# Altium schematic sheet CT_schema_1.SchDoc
size 540 x 499 mm
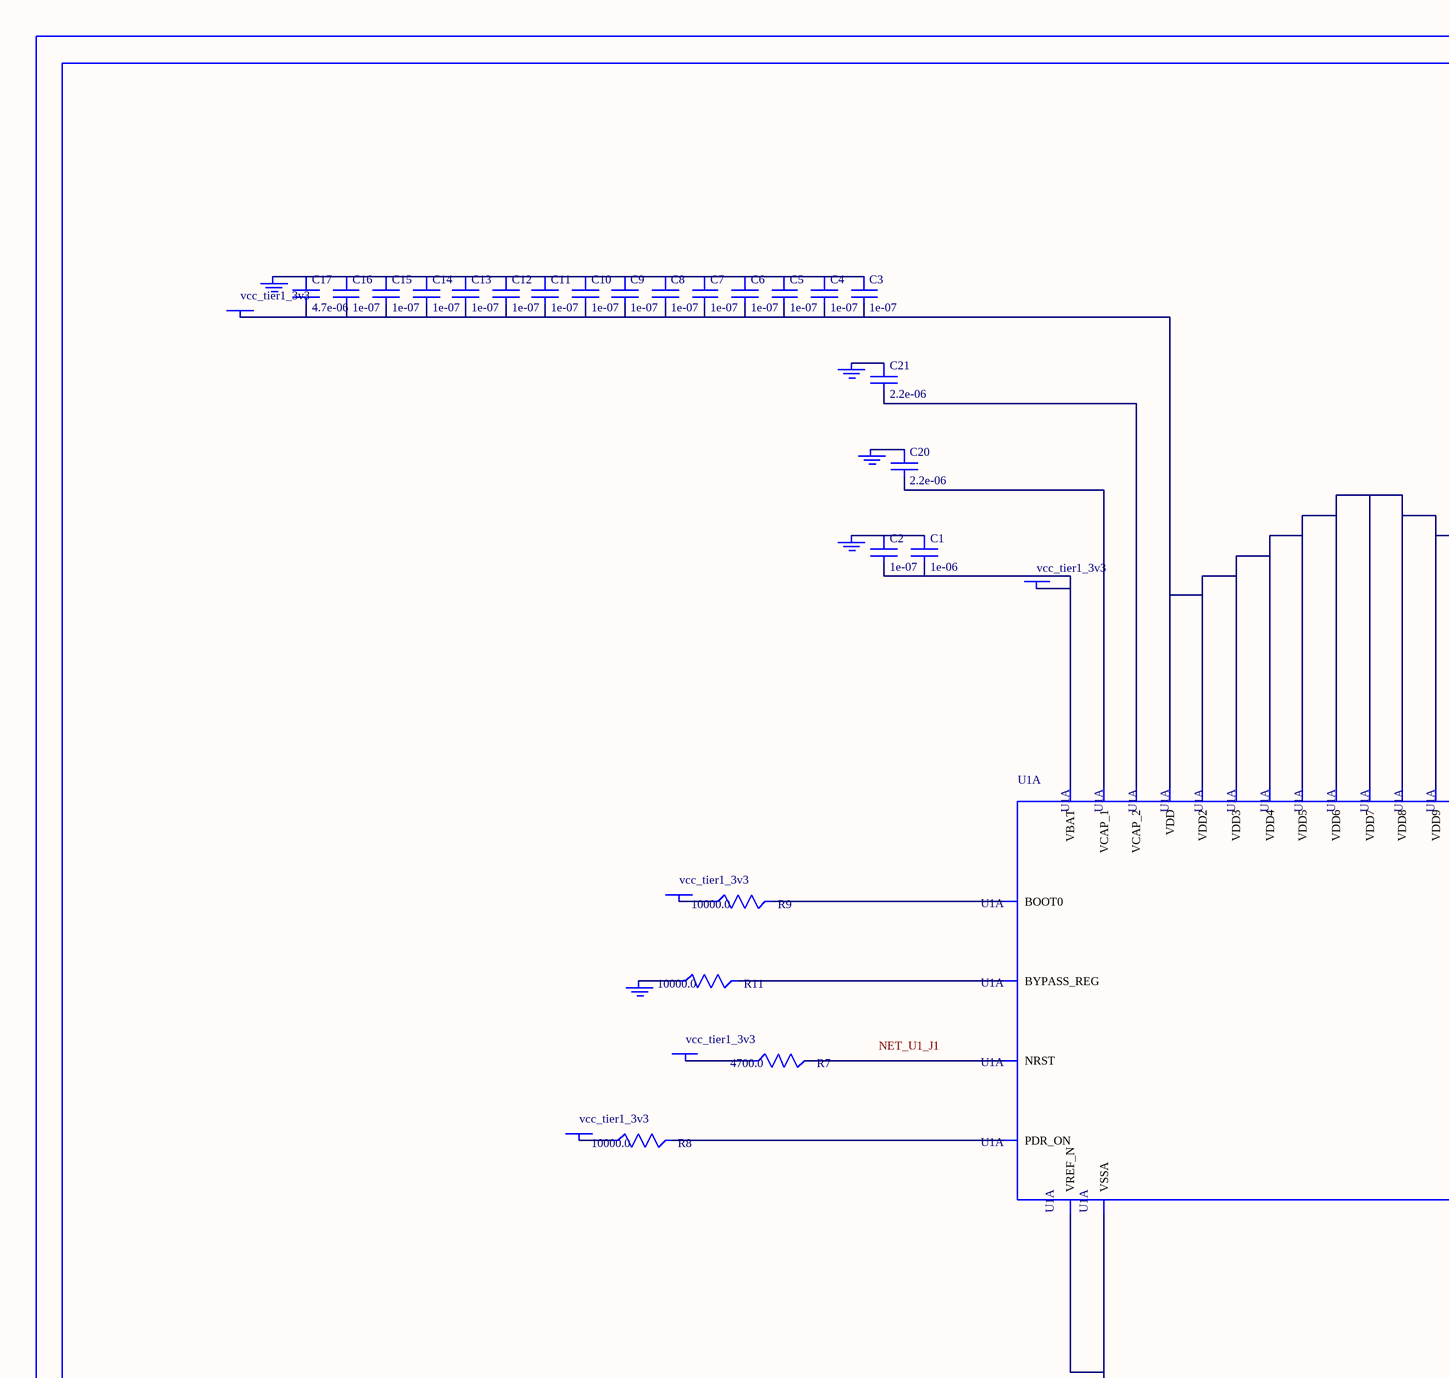
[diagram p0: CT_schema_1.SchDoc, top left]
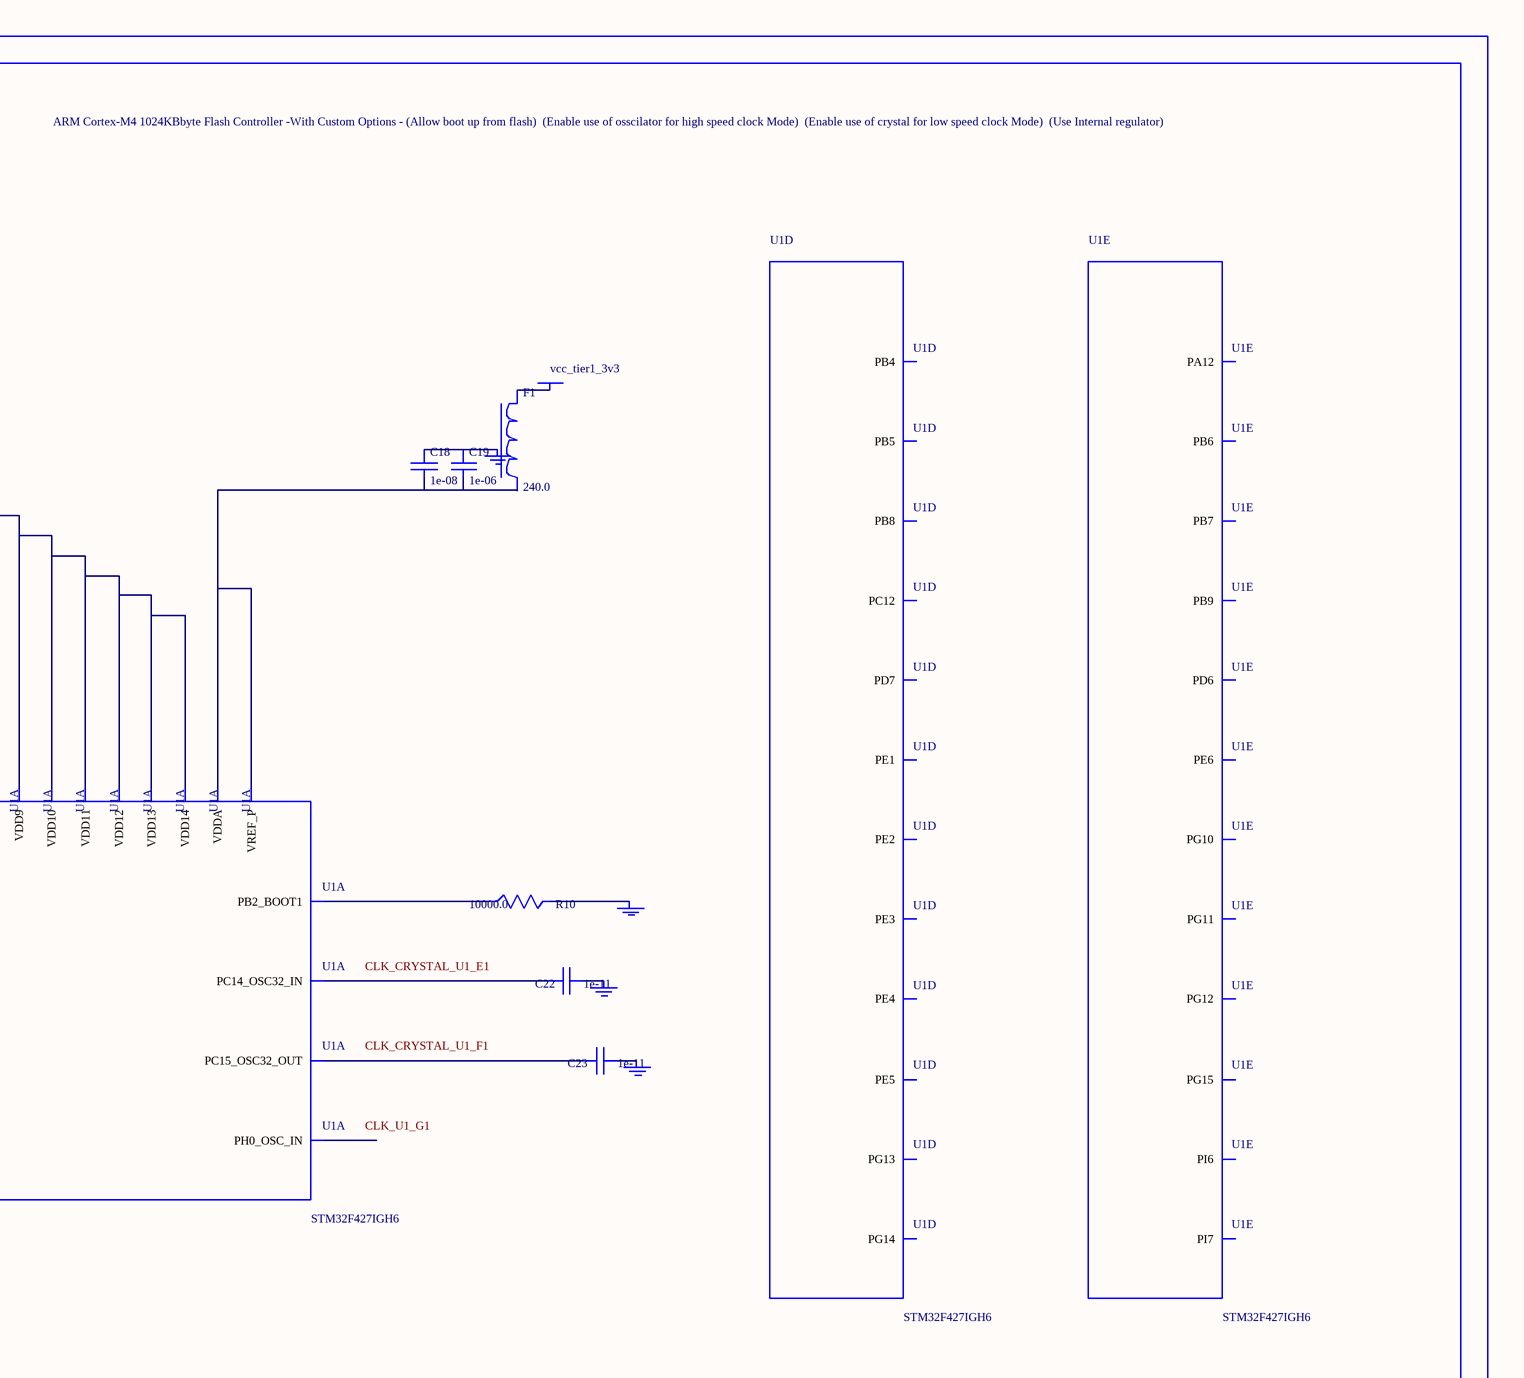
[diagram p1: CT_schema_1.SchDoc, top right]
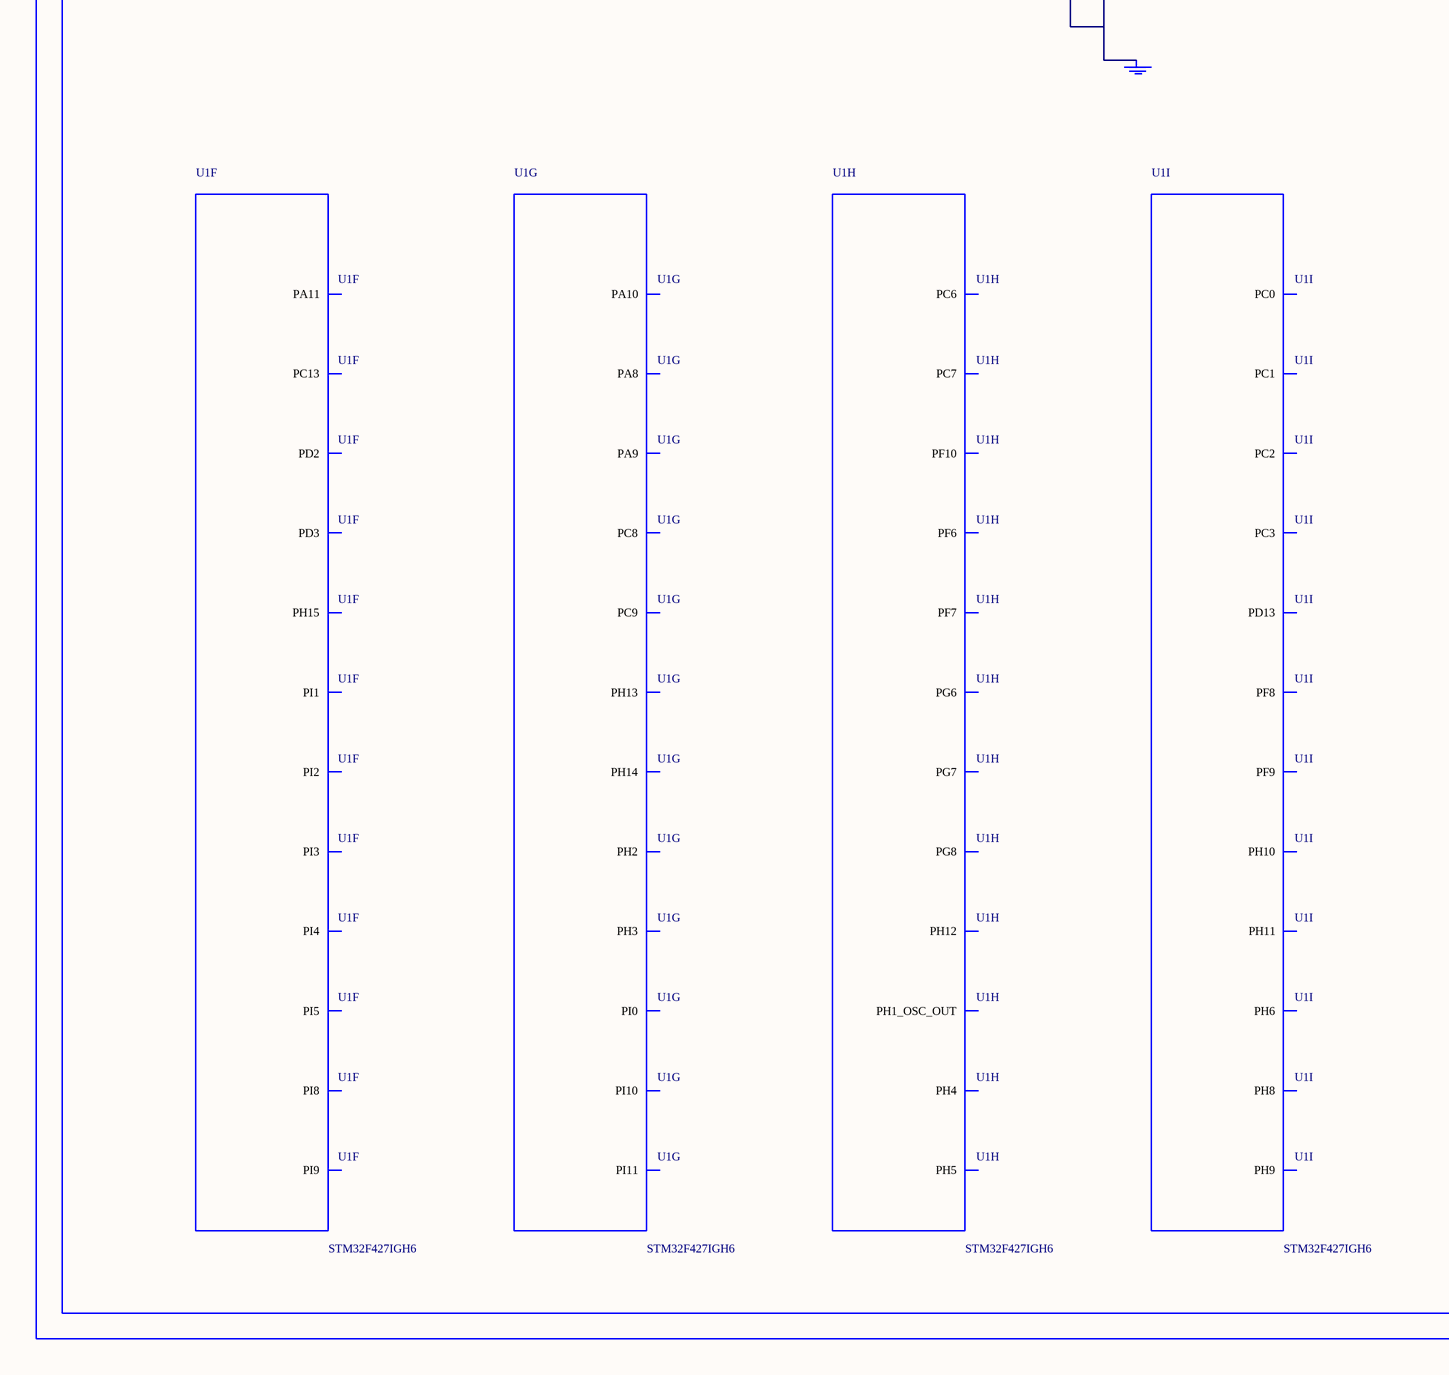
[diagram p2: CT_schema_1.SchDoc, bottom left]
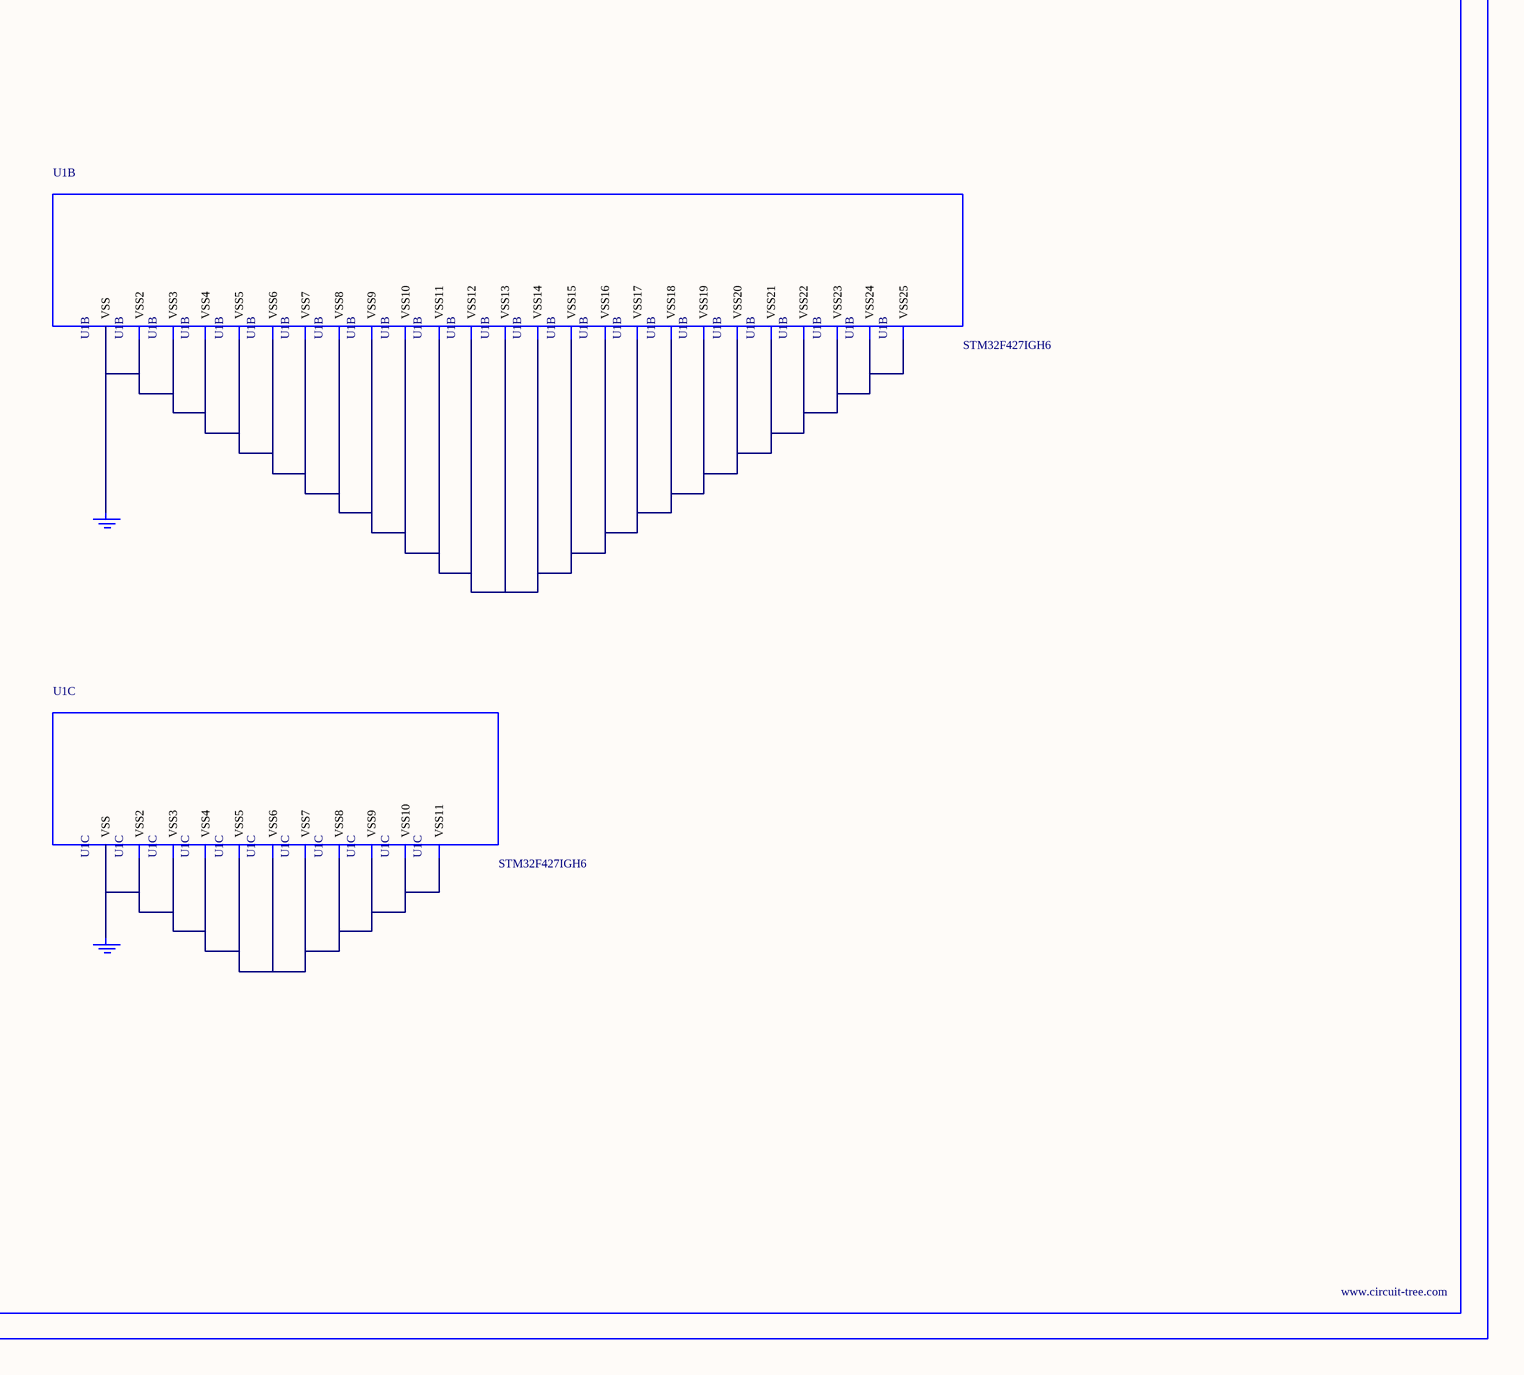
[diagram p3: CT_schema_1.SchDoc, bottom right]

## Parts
BORDER0  (no value)
C1  1e-06  [C0603]
C2  1e-07  [C0603]
C3  1e-07  [C0603]
C4  1e-07  [C0603]
C5  1e-07  [C0603]
C6  1e-07  [C0603]
C7  1e-07  [C0603]
C8  1e-07  [C0603]
C9  1e-07  [C0603]
C10  1e-07  [C0603]
C11  1e-07  [C0603]
C12  1e-07  [C0603]
C13  1e-07  [C0603]
C14  1e-07  [C0603]
C15  1e-07  [C0603]
C16  1e-07  [C0603]
C17  4.7e-06  [C0603]
C18  1e-08  [C0603]
C19  1e-06  [C0603]
C20  2.2e-06  [C0603]
C21  2.2e-06  [C0603]
C22  1e-11  [C0402]
C23  1e-11  [C0402]
F1  240.0  [L0603]
GND_INSTANCE_0_0  (no value)
GND_INSTANCE_0_1  (no value)
GND_INSTANCE_0_2  (no value)
GND_INSTANCE_0_3  (no value)
GND_INSTANCE_0_4  (no value)
GND_INSTANCE_0_5  (no value)
GND_INSTANCE_0_6  (no value)
GND_INSTANCE_0_7  (no value)
GND_INSTANCE_0_8  (no value)
GND_INSTANCE_0_9  (no value)
GND_INSTANCE_0_10  (no value)
GND_INSTANCE_0_11  (no value)
POWER_INSTANCE_0_0  vcc_tier1_3v3
POWER_INSTANCE_0_1  vcc_tier1_3v3
POWER_INSTANCE_0_2  vcc_tier1_3v3
POWER_INSTANCE_0_3  vcc_tier1_3v3
POWER_INSTANCE_0_4  vcc_tier1_3v3
POWER_INSTANCE_0_5  vcc_tier1_3v3
R7  4700.0  [R0603]
R8  10000.0  [R0603]
R9  10000.0  [R0603]
R10  10000.0  [R0603]
R11  10000.0  [R0603]
U1  STM32F427IGH6  [UFBGA176_25]  (parts A,B,C,D,E,F,G,H,I of 16)

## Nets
NetC1_1: C1.1 C2.1 GND_INSTANCE_0_0.0(GND)
NetC1_2: C1.2 C2.2 POWER_INSTANCE_0_0.0(PWR) U1.C1(VBAT)
NetC3_1: C3.1 C4.1 C5.1 C6.1 C7.1 C8.1 C9.1 C10.1 C11.1 C12.1 C13.1 C14.1 C15.1 C16.1 C17.1 GND_INSTANCE_0_2.0(GND)
NetC3_2: C3.2 C4.2 C5.2 C6.2 C7.2 C8.2 C9.2 C10.2 C11.2 C12.2 C13.2 C14.2 C15.2 C16.2 C17.2 POWER_INSTANCE_0_2.0(PWR) U1.C5(VDD) U1.C7(VDD2) U1.C8(VDD3) U1.C9(VDD4) U1.F3(VDD5) U1.G3(VDD7) U1.G13(VDD6) U1.H13(VDD8) U1.J12(VDD9) U1.J13(VDD10) U1.K4(VDD11) U1.N8(VDD13) U1.N9(VDD14) U1.N10(VDD12)
NetC18_1: C18.1 C19.1 GND_INSTANCE_0_1.0(GND)
NetC18_2: C18.2 C19.2 U1.P1(VREF_P) U1.R1(VDDA)
NetC20_1: C20.1 GND_INSTANCE_0_5.0(GND)
NetC20_2: C20.2 U1.M10(VCAP_1)
NetC21_1: C21.1 GND_INSTANCE_0_6.0(GND)
NetC21_2: C21.2 U1.F13(VCAP_2)
NetC22_1: C22.1 GND_INSTANCE_0_7.0(GND)
NetC22_2: C22.2 U1.E1(PC14_OSC32_IN)
NetC23_1: C23.1 GND_INSTANCE_0_8.0(GND)
NetC23_2: C23.2 U1.F1(PC15_OSC32_OUT)
NetF1_1: F1.1 POWER_INSTANCE_0_1.0(PWR)
NetGND_INSTANCE_0_3_0: GND_INSTANCE_0_3.0(GND) R10.2
NetGND_INSTANCE_0_4_0: GND_INSTANCE_0_4.0(GND) R11.1
NetGND_INSTANCE_0_9_0: GND_INSTANCE_0_9.0(GND) U1.M1(VSSA) U1.N1(VREF_N)
NetGND_INSTANCE_0_10_0: GND_INSTANCE_0_10.0(GND) U1.D5(VSS) U1.D7(VSS2) U1.D8(VSS3) U1.D9(VSS4) U1.F2(VSS7) U1.F6(VSS8) U1.F7(VSS9) U1.F8(VSS10) U1.F9(VSS11) U1.F10(VSS5) U1.F12(VSS6) U1.G2(VSS14) U1.G6(VSS15) U1.G7(VSS16) U1.G8(VSS17) U1.G9(VSS18) U1.G10(VSS12) U1.G12(VSS13) U1.H6(VSS21) U1.H7(VSS22) U1.H8(VSS23) U1.H9(VSS24) U1.H10(VSS19) U1.H12(VSS20) U1.J10(VSS25)
NetGND_INSTANCE_0_11_0: GND_INSTANCE_0_11.0(GND) U1.J6(VSS) U1.J7(VSS2) U1.J8(VSS3) U1.J9(VSS4) U1.K6(VSS6) U1.K7(VSS7) U1.K8(VSS8) U1.K9(VSS9) U1.K10(VSS5) U1.M8(VSS10) U1.M9(VSS11)
NetPOWER_INSTANCE_0_3_0: POWER_INSTANCE_0_3.0(PWR) R8.1
NetPOWER_INSTANCE_0_4_0: POWER_INSTANCE_0_4.0(PWR) R9.1
NetPOWER_INSTANCE_0_5_0: POWER_INSTANCE_0_5.0(PWR) R7.1
NetR7_2: R7.2 U1.J1(NRST)
NetR8_2: R8.2 U1.C6(PDR_ON)
NetR9_2: R9.2 U1.D6(BOOT0)
NetR10_1: R10.1 U1.M6(PB2_BOOT1)
NetR11_2: R11.2 U1.L4(BYPASS_REG)

Not connected (* = marked no-connect by the designer): F1 2; U1 A1(PE3) A2(PE2) A3(PE1) A5(PB8) A6(PB5) A7(PG14) A8(PG13) A9(PB4) A11(PD7) A12(PC12) B1(PE4) B2(PE5) B3(PE6) B4(PB9) B5(PB7) B6(PB6) B7(PG15) B8(PG12) B9(PG11) B10(PG10) B11(PD6) B15(PA12) C2(PI7) C3(PI6) C4(PI5) C13(PI3) C14(PI2) C15(PA11) D1(PC13) D2(PI8) D3(PI9) D4(PI4) D11(PD3) D12(PD2) D13(PH15) D14(PI1) D15(PA10) E3(PI10) E4(PI11) E12(PH13) E13(PH14) E14(PI0) E15(PA9) F4(PH2) F14(PC9) F15(PA8) G1(PH0_OSC_IN) G4(PH3) G14(PC8) G15(PC7) H1(PH1_OSC_OUT) H4(PH4) H14(PG8) H15(PC6) J4(PH5) J14(PG7) J15(PG6) K1(PF7) K2(PF6) K12(PH12) L1(PF10) L2(PF9) L3(PF8) L12(PH11) L13(PH10) M2(PC0) M3(PC1) M4(PC2) M5(PC3) M11(PH6) M12(PH8) M13(PH9) M15(PD13)

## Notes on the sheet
- Labels drawn without touching a wire or pin: CLK_CRYSTAL_U1_E1, CLK_CRYSTAL_U1_F1, CLK_U1_G1, NET_U1_J1

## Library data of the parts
BORDER0 = BORDER_PAGE0
C1 C19 = C0603C105K3RACTU
C2-C16 = 06035C104K4Z2A
C17 = GRM188R6YA475KE15D
C18 = 06035C103K4Z2A
C20 C21 = C0603C225K8RACTU
C22 C23 = C0402C100K3GACTU
F1 = Z0603C241ASMST
GND_INSTANCE_0_0-GND_INSTANCE_0_11 = GND
POWER_INSTANCE_0_0-POWER_INSTANCE_0_5 = PWR
R7 = RC0603JR-074K7L
R8-R11 = RC0603JR-0710KL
